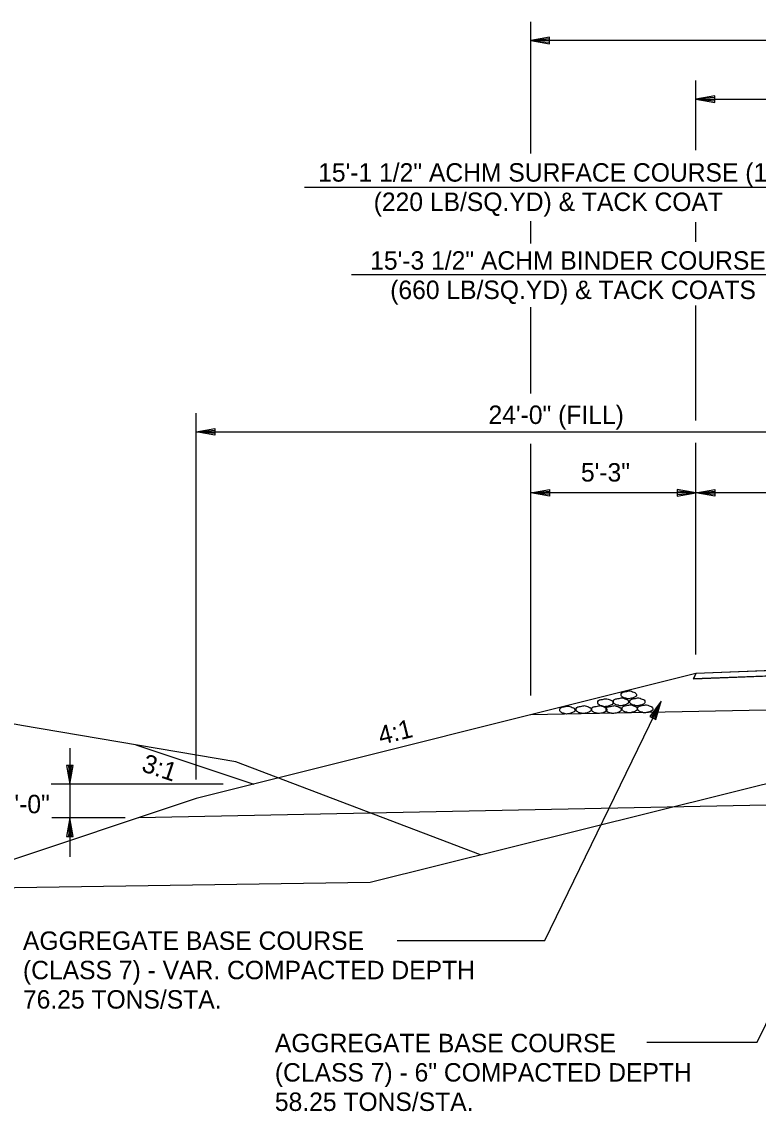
# Model space of a CAD drawing. Extents: x 1398565 to 1398920, y 1968324 to 1968581.
# Drawn here: x 1398801.17 to 1398824.75, y 1968541.66 to 1968576.55 of the extents above; entities that cross this region are included whole.
import ezdxf

# ---------------------------------------------------------------- set-up
doc = ezdxf.new("R2010")
doc.units = 0
for name, color, linetype in [('1', 7, 'Continuous'), ('10', 7, 'Continuous'), ('19', 7, 'Continuous'), ('42', 7, 'Continuous'), ('Default', 7, 'Continuous')]:
    doc.layers.add(name, color=color, linetype=linetype)

# ---------------------------------------------------------------- blocks, each defined once
blk = doc.blocks.new('ROCKS')
at = {"layer": '1'}
blk.add_spline([(0.013, 0.06), (0.053, 0.053), (0.107, 0.033), (0.133, 0.013), (0.133, -0.007), (0.12, -0.033), (0.107, -0.04), (0.073, -0.053), (0.033, -0.067), (0.013, -0.067), (-0.02, -0.06), (-0.06, -0.053), (-0.087, -0.047), (-0.113, -0.02), (-0.113, -0.007), (-0.107, 0.02), (-0.087, 0.033), (-0.067, 0.047), (-0.033, 0.053), (-0.02, 0.06), (0.013, 0.06)], degree=3, dxfattribs=at)
blk = doc.blocks.new('4TO1 ABC')
at = {"layer": '1', "xscale": 0.1312491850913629, "yscale": 0.1312491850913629, "rotation": 180}
for p in [(0.00175, -0.00875), (-0.016625, -0.023625), (0.018375, -0.023625), (0.051625, -0.025375), (-0.03325, -0.0385), (0, -0.0385), (0.034125, -0.04025), (0.06475, -0.04025), (0.098, -0.04025), (0.133, -0.041125)]:
    blk.add_blockref('ROCKS', p, dxfattribs=at)

msp = doc.modelspace()

# ---------------------------------------------------------------- linework, layer by layer
at = {"layer": '19'}
for p, q in [((1398817.47, 1968572.333), (1398817.47, 1968576.547)), ((1398818.07, 1968576.052), (1398817.47, 1968575.947)), ((1398818.07, 1968575.842), (1398818.07, 1968576.052)), ((1398843.753, 1968575.947), (1398817.47, 1968575.947)), ((1398817.47, 1968575.947), (1398818.07, 1968575.842)), ((1398818.07, 1968575.997), (1398817.63, 1968575.962)), ((1398817.63, 1968575.932), (1398818.07, 1968575.892)), ((1398822.753, 1968572.438), (1398822.753, 1968574.672)), ((1398823.353, 1968574.177), (1398822.753, 1968574.072)), ((1398822.753, 1968574.072), (1398862.753, 1968574.072)), ((1398822.753, 1968574.072), (1398823.353, 1968573.967)), ((1398823.353, 1968574.122), (1398822.913, 1968574.087)), ((1398822.913, 1968574.057), (1398823.353, 1968574.017)), ((1398823.353, 1968573.967), (1398823.353, 1968574.177)), ((1398810.228, 1968571.25), (1398843.753, 1968571.25)), ((1398817.47, 1968569.452), (1398817.47, 1968570.159)), ((1398822.753, 1968569.504), (1398822.753, 1968570.133)), ((1398811.73, 1968568.452), (1398843.753, 1968568.452)), ((1398817.47, 1968564.643), (1398817.47, 1968567.409)), ((1398822.753, 1968563.783), (1398822.753, 1968567.461)), ((1398806.753, 1968552.29), (1398806.753, 1968564.017)), ((1398806.753, 1968563.417), (1398807.353, 1968563.522)), ((1398806.913, 1968563.432), (1398807.353, 1968563.467)), ((1398807.353, 1968563.522), (1398807.353, 1968563.312)), ((1398806.753, 1968563.417), (1398830.753, 1968563.417)), ((1398807.353, 1968563.312), (1398806.753, 1968563.417)), ((1398807.353, 1968563.362), (1398806.913, 1968563.402)), ((1398817.47, 1968554.978), (1398817.47, 1968563.035)), ((1398822.753, 1968556.292), (1398822.753, 1968563.061)), ((1398817.47, 1968561.463), (1398818.07, 1968561.568)), ((1398830.753, 1968561.463), (1398817.47, 1968561.463)), ((1398818.07, 1968561.358), (1398817.47, 1968561.463)), ((1398817.63, 1968561.478), (1398818.07, 1968561.513)), ((1398818.07, 1968561.408), (1398817.63, 1968561.448)), ((1398818.07, 1968561.568), (1398818.07, 1968561.358)), ((1398822.153, 1968561.568), (1398822.153, 1968561.358)), ((1398822.753, 1968561.463), (1398822.153, 1968561.568)), ((1398822.593, 1968561.478), (1398822.153, 1968561.513)), ((1398822.153, 1968561.358), (1398822.753, 1968561.463)), ((1398822.153, 1968561.408), (1398822.593, 1968561.448)), ((1398822.753, 1968561.463), (1398823.353, 1968561.568)), ((1398823.353, 1968561.358), (1398822.753, 1968561.463)), ((1398822.913, 1968561.478), (1398823.353, 1968561.513)), ((1398823.353, 1968561.408), (1398822.913, 1968561.448)), ((1398823.353, 1968561.568), (1398823.353, 1968561.358)), ((1398828.753, 1968555.914), (1398822.753, 1968555.674)), ((1398822.753, 1968555.674), (1398806.753, 1968551.672)), ((1398828.753, 1968555.747), (1398822.668, 1968555.503)), ((1398822.753, 1968555.674), (1398822.668, 1968555.503)), ((1398842.753, 1968554.858), (1398817.47, 1968554.352)), ((1398817.914, 1968547.132), (1398821.642, 1968554.79)), ((1398821.642, 1968554.79), (1398821.279, 1968554.302)), ((1398821.466, 1968554.209), (1398821.642, 1968554.79)), ((1398824.713, 1968543.872), (1398830.051, 1968554.837)), ((1398821.56, 1968554.654), (1398821.327, 1968554.28)), ((1398821.422, 1968554.232), (1398821.585, 1968554.641)), ((1398821.279, 1968554.302), (1398821.466, 1968554.209)), ((1398804.825, 1968553.395), (1398808.605, 1968552.135)), ((1398802.714, 1968553.293), (1398802.714, 1968552.017)), ((1398802.819, 1968552.735), (1398802.609, 1968552.735)), ((1398802.609, 1968552.735), (1398802.714, 1968552.135)), ((1398802.664, 1968552.735), (1398802.699, 1968552.295)), ((1398802.714, 1968552.135), (1398802.819, 1968552.735)), ((1398802.729, 1968552.295), (1398802.769, 1968552.735)), ((1398802.714, 1968552.017), (1398802.714, 1968549.811)), ((1398806.753, 1968551.672), (1398798.077, 1968548.78)), ((1398843.753, 1968551.838), (1398804.922, 1968551.061)), ((1398802.714, 1968551.061), (1398802.609, 1968550.461)), ((1398802.699, 1968550.901), (1398802.664, 1968550.461)), ((1398802.819, 1968550.461), (1398802.714, 1968551.061)), ((1398802.769, 1968550.461), (1398802.729, 1968550.901)), ((1398802.609, 1968550.461), (1398802.819, 1968550.461)), ((1398813.186, 1968547.132), (1398817.914, 1968547.132)), ((1398821.185, 1968543.872), (1398824.713, 1968543.872))]:
    msp.add_line(p, q, dxfattribs=at)
msp.add_lwpolyline([(1398822.671, 1968555.508), (1398828.753, 1968555.747), (1398842.753, 1968556.027), (1398856.753, 1968555.747), (1398862.838, 1968555.503), (1398862.753, 1968555.674), (1398856.753, 1968555.914), (1398842.753, 1968556.194), (1398828.753, 1968555.914), (1398822.753, 1968555.674)], close=True, dxfattribs=at)
at = {"layer": '42'}
for points in [[(1398766.812, 1968548.312), (1398812.323, 1968548.993), (1398816.74, 1968550.093), (1398837.753, 1968555.327), (1398843.753, 1968555.567)], [(1398815.853, 1968549.872), (1398808.022, 1968552.85), (1398801.167, 1968554.018), (1398797.201, 1968554.737), (1398793.998, 1968555.048), (1398790.661, 1968555.193), (1398785.193, 1968554.732), (1398776.174, 1968554.74), (1398764.998, 1968554.785)]]:
    msp.add_lwpolyline(points, dxfattribs=at)
at = {"layer": 'Default'}
for p, q in [((1398807.62, 1968552.135), (1398802.119, 1968552.135)), ((1398804.485, 1968551.061), (1398802.133, 1968551.061))]:
    msp.add_line(p, q, dxfattribs=at)

# ---------------------------------------------------------------- block references
at = {"layer": '19', "xscale": 14.999970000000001, "yscale": -14.999970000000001, "rotation": 180}
msp.add_blockref('4TO1 ABC', (1398820.61, 1968555.12), dxfattribs=at)

# ---------------------------------------------------------------- texts
at = {"layer": '10'}
for s, height, rotation, p in [('24\'-0" (FILL)', 0.59001, 360, (1398816.113, 1968563.669)), ('5\'-3"', 0.59, 360, (1398819.072, 1968561.826)), ('4:1', 0.59, 13.7364, (1398812.665, 1968553.392)), ('3:1', 0.59, 341.5224, (1398804.975, 1968552.56)), ('1\'-0"', 0.59, 360, (1398800.499, 1968551.204))]:
    msp.add_text(s, height=height, rotation=rotation, dxfattribs=at).set_placement(p)
at = {"layer": '19'}
for s, p in [('AGGREGATE BASE COURSE', (1398801.211, 1968546.829)), ('(CLASS 7) - VAR. COMPACTED DEPTH', (1398801.211, 1968545.889)), ('76.25 TONS/STA.', (1398801.211, 1968544.949)), ('AGGREGATE BASE COURSE', (1398809.275, 1968543.552)), ('(CLASS 7) - 6" COMPACTED DEPTH', (1398809.275, 1968542.612)), ('58.25 TONS/STA.', (1398809.275, 1968541.672))]:
    msp.add_text(s, height=0.59001, rotation=360, dxfattribs=at).set_placement(p)
at = {"layer": '42'}
for s, p in [('15\'-1 1/2" ACHM SURFACE COURSE (1/2")', (1398810.661, 1968571.429)), ('(220 LB/SQ.YD) & TACK COAT', (1398812.438, 1968570.489)), ('15\'-3 1/2" ACHM BINDER COURSE (1")', (1398812.326, 1968568.61)), ('(660 LB/SQ.YD) & TACK COATS', (1398812.967, 1968567.67))]:
    msp.add_text(s, height=0.59001, rotation=360, dxfattribs=at).set_placement(p)

doc.saveas('drawing.dxf')
